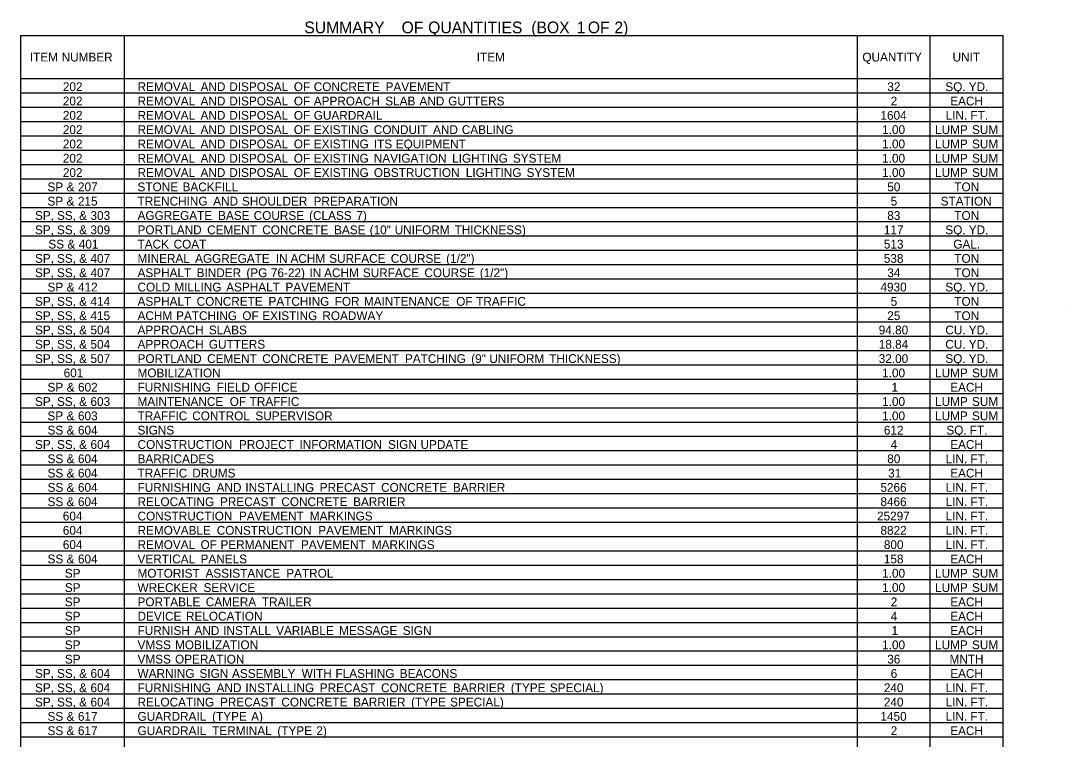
# Model space of a CAD drawing. Extents: x 107 to 7866, y 32 to 1473.
# Drawn here: x 6428 to 7140, y 553 to 1043 of the extents above; entities that cross this region are included whole.
import ezdxf

# ---------------------------------------------------------------- set-up
doc = ezdxf.new("R2010")
doc.units = 0
doc.layers.add('Default', color=7, linetype='Continuous')

msp = doc.modelspace()

# ---------------------------------------------------------------- linework, layer by layer
at = {"layer": 'Default'}
for p, q in [((6427.83, 1032.7), (7097.17, 1032.7)), ((6427.83, 67.45), (6427.83, 1032.7)), ((6427.83, 67.45), (6427.83, 1032.7)), ((6498.52, 155.2), (6498.52, 1032.7)), ((6997.72, 1032.7), (7097.17, 1032.7)), ((6997.72, 67.45), (6997.72, 1032.7)), ((7047.45, 67.45), (7047.45, 1032.7)), ((7047.45, 155.2), (7047.45, 1032.7)), ((7097.17, 67.45), (7097.17, 1032.7)), ((6427.83, 1003.45), (7097.17, 1003.45)), ((6427.83, 1003.45), (7097.17, 1003.45)), ((6498.52, 340.45), (6498.52, 1003.45)), ((6997.72, 340.45), (6997.72, 1003.45)), ((6427.83, 993.7), (7097.17, 993.7)), ((6427.83, 983.95), (7097.17, 983.95)), ((6427.83, 974.2), (7097.17, 974.2)), ((6427.83, 964.45), (7097.17, 964.45)), ((6427.83, 954.7), (7097.17, 954.7)), ((6427.83, 944.95), (7097.17, 944.95)), ((6427.83, 935.2), (7097.17, 935.2)), ((6427.83, 925.45), (7097.17, 925.45)), ((6427.83, 915.7), (7097.17, 915.7)), ((6427.83, 905.95), (7097.17, 905.95)), ((6427.83, 896.2), (7097.17, 896.2)), ((6427.83, 886.45), (7097.17, 886.45)), ((6427.83, 876.7), (7097.17, 876.7)), ((6427.83, 866.95), (7097.17, 866.95)), ((6427.83, 857.2), (7097.17, 857.2)), ((6427.83, 847.45), (7097.17, 847.45)), ((7139.96, 848.72), (7139.96, 848.72)), ((6427.83, 837.7), (7097.17, 837.7)), ((6427.83, 827.95), (7097.17, 827.95)), ((6427.83, 818.2), (7097.17, 818.2)), ((6427.83, 808.45), (7097.17, 808.45)), ((6427.83, 798.7), (7097.17, 798.7)), ((6427.83, 788.95), (7097.17, 788.95)), ((6427.83, 779.2), (7097.17, 779.2)), ((6427.83, 769.45), (7097.17, 769.45)), ((6427.83, 759.7), (7097.17, 759.7)), ((6427.83, 749.95), (7097.17, 749.95)), ((6427.83, 740.2), (7097.17, 740.2)), ((6427.83, 730.45), (7097.17, 730.45)), ((6427.83, 720.7), (7097.17, 720.7)), ((6427.83, 710.95), (7097.17, 710.95)), ((6427.83, 701.2), (7097.17, 701.2)), ((6427.83, 691.45), (7097.17, 691.45)), ((6427.83, 681.7), (7097.17, 681.7)), ((6427.83, 671.95), (7097.17, 671.95)), ((6427.83, 662.2), (7097.17, 662.2)), ((6427.83, 652.45), (7097.17, 652.45)), ((6427.83, 642.7), (7097.17, 642.7)), ((6427.83, 632.95), (7097.17, 632.95)), ((6427.83, 623.2), (7097.17, 623.2)), ((6427.83, 613.45), (7097.17, 613.45)), ((6427.83, 603.7), (7097.17, 603.7)), ((6427.83, 593.95), (7097.17, 593.95)), ((6427.83, 584.2), (7097.17, 584.2)), ((6427.83, 574.45), (7097.17, 574.45)), ((6427.83, 564.7), (7097.17, 564.7)), ((6427.83, 554.95), (7097.17, 554.95))]:
    msp.add_line(p, q, dxfattribs=at)

# ---------------------------------------------------------------- texts
for s, height, p in [('                                          SUMMARY', 8, (6496.1, 1034.3)), (' OF', 8, (6684.23, 1034.3)), (' QUANTITIES', 8, (6702.34, 1034.3)), (' (BOX', 8, (6772.59, 1034.3)), (' 1', 8, (6803.63, 1034.3)), (' OF', 8, (6811.13, 1034.3)), (' 2)', 8, (6829.24, 1034.3)), ('ITEM', 6, (6433.92, 1015.08)), (' NUMBER', 6, (6453.35, 1015.08)), ('ITEM', 6, (6738.41, 1015.08)), ('QUANTITY', 6, (7001.15, 1015.08)), ('UNIT', 6, (7062.62, 1015.08)), ('202', 6, (6456.41, 994.9)), ('REMOVAL', 6, (6507.3, 994.9)), (' AND', 6, (6548, 994.9)), (' DISPOSAL', 6, (6567.58, 994.9)), (' OF', 6, (6611.55, 994.9)), (' CONCRETE', 6, (6625.13, 994.9)), (' PAVEMENT', 6, (6674.06, 994.9)), ('32', 6, (7018.14, 994.9)), ('SQ.', 6, (7057.67, 994.9)), (' YD.', 6, (7071.38, 994.9)), ('202', 6, (6456.41, 985.15)), ('REMOVAL', 6, (6507.3, 985.15)), (' AND', 6, (6548, 985.15)), (' DISPOSAL', 6, (6567.58, 985.15)), (' OF', 6, (6611.55, 985.15)), (' APPROACH', 6, (6625.13, 985.15)), (' SLAB', 6, (6673.84, 985.15)), (' AND', 6, (6697.16, 985.15)), (' GUTTERS', 6, (6716.74, 985.15)), ('2', 6, (7020.47, 985.15)), ('EACH', 6, (7061, 985.15)), ('202', 6, (6456.41, 975.4)), ('REMOVAL', 6, (6507.3, 975.4)), (' AND', 6, (6548, 975.4)), (' DISPOSAL', 6, (6567.58, 975.4)), (' OF', 6, (6611.55, 975.4)), (' GUARDRAIL', 6, (6625.13, 975.4)), ('1604', 6, (7013.47, 975.4)), ('LIN.', 6, (7057.9, 975.4)), (' FT.', 6, (7072.54, 975.4)), ('202', 6, (6456.41, 965.65)), ('REMOVAL', 6, (6507.3, 965.65)), (' AND', 6, (6548, 965.65)), (' DISPOSAL', 6, (6567.58, 965.65)), (' OF', 6, (6611.55, 965.65)), (' EXISTING', 6, (6625.13, 965.65)), (' CONDUIT', 6, (6666.07, 965.65)), (' AND', 6, (6706.42, 965.65)), (' CABLING', 6, (6726, 965.65)), ('1.00', 6, (7014.63, 965.65)), ('LUMP', 6, (7050.68, 965.65)), (' SUM', 6, (7073.61, 965.65)), ('202', 6, (6456.41, 955.9)), ('REMOVAL', 6, (6507.3, 955.9)), (' AND', 6, (6548, 955.9)), (' DISPOSAL', 6, (6567.58, 955.9)), (' OF', 6, (6611.55, 955.9)), (' EXISTING', 6, (6625.13, 955.9)), (' ITS', 6, (6666.07, 955.9)), (' EQUIPMENT', 6, (6681, 955.9)), ('1.00', 6, (7014.63, 955.9)), ('LUMP', 6, (7050.68, 955.9)), (' SUM', 6, (7073.61, 955.9)), ('202', 6, (6456.41, 946.15)), ('REMOVAL', 6, (6507.3, 946.15)), (' AND', 6, (6548, 946.15)), (' DISPOSAL', 6, (6567.58, 946.15)), (' OF', 6, (6611.55, 946.15)), (' EXISTING', 6, (6625.13, 946.15)), (' NAVIGATION', 6, (6666.07, 946.15)), (' LIGHTING', 6, (6719.42, 946.15)), (' SYSTEM', 6, (6760.81, 946.15)), ('1.00', 6, (7014.63, 946.15)), ('LUMP', 6, (7050.68, 946.15)), (' SUM', 6, (7073.61, 946.15)), ('202', 6, (6456.41, 936.4)), ('REMOVAL', 6, (6507.3, 936.4)), (' AND', 6, (6548, 936.4)), (' DISPOSAL', 6, (6567.58, 936.4)), (' OF', 6, (6611.55, 936.4)), (' EXISTING', 6, (6625.13, 936.4)), (' OBSTRUCTION', 6, (6666.07, 936.4)), (' LIGHTING', 6, (6728.73, 936.4)), (' SYSTEM', 6, (6770.12, 936.4)), ('1.00', 6, (7014.63, 936.4)), ('LUMP', 6, (7050.68, 936.4)), (' SUM', 6, (7073.61, 936.4)), ('SP', 6, (6445.94, 926.65)), (' &', 6, (6456.76, 926.65)), (' 207', 6, (6464.49, 926.65)), ('STONE', 6, (6507.3, 926.65)), (' BACKFILL', 6, (6535.73, 926.65)), ('50', 6, (7018.12, 926.65)), ('TON', 6, (7063.8, 926.65)), ('SP', 6, (6445.92, 916.9)), (' &', 6, (6456.74, 916.9)), (' 215', 6, (6464.46, 916.9)), ('TRENCHING', 6, (6507.3, 916.9)), (' AND', 6, (6556.61, 916.9)), (' SHOULDER', 6, (6576.19, 916.9)), (' PREPARATION', 6, (6624.99, 916.9)), ('5', 6, (7020.42, 916.9)), ('STATION', 6, (7054.48, 916.9)), ('SP,', 6, (6437.42, 907.15)), (' SS,', 6, (6450.18, 907.15)), (' &', 6, (6465.28, 907.15)), (' 303', 6, (6473.01, 907.15)), ('AGGREGATE', 6, (6507.3, 907.15)), (' BASE', 6, (6559.96, 907.15)), (' COURSE', 6, (6584.21, 907.15)), (' (CLASS', 6, (6621.96, 907.15)), (' 7)', 6, (6654.14, 907.15)), ('83', 6, (7018.11, 907.15)), ('TON', 6, (7063.8, 907.15)), ('SP,', 6, (6437.41, 897.4)), (' SS,', 6, (6450.18, 897.4)), (' &', 6, (6465.28, 897.4)), (' 309', 6, (6473, 897.4)), ('PORTLAND', 6, (6507.3, 897.4)), (' CEMENT', 6, (6552.5, 897.4)), (' CONCRETE', 6, (6590.06, 897.4)), (' BASE', 6, (6638.99, 897.4)), (' (10"', 6, (6663.24, 897.4)), (' UNIFORM', 6, (6680.26, 897.4)), (' THICKNESS)', 6, (6721.08, 897.4)), ('117', 6, (7015.78, 897.4)), ('SQ.', 6, (7057.67, 897.4)), (' YD.', 6, (7071.38, 897.4)), ('SS', 6, (6446.56, 887.65)), (' &', 6, (6457.3, 887.65)), (' 401', 6, (6465.03, 887.65)), ('TACK', 6, (6507.3, 887.65)), (' COAT', 6, (6529.64, 887.65)), ('513', 6, (7015.78, 887.65)), ('GAL.', 6, (7063.12, 887.65)), ('SP,', 6, (6437.42, 877.9)), (' SS,', 6, (6450.18, 877.9)), (' &', 6, (6465.28, 877.9)), (' 407', 6, (6473.01, 877.9)), ('MINERAL', 6, (6507.3, 877.9)), (' AGGREGATE', 6, (6544.26, 877.9)), (' IN', 6, (6599.26, 877.9)), (' ACHM', 6, (6609.28, 877.9)), (' SURFACE', 6, (6635.66, 877.9)), (' COURSE', 6, (6677.61, 877.9)), (' (1/2")', 6, (6715.36, 877.9)), ('538', 6, (7015.78, 877.9)), ('TON', 6, (7063.8, 877.9)), ('SP,', 6, (6437.42, 868.15)), (' SS,', 6, (6450.18, 868.15)), (' &', 6, (6465.28, 868.15)), (' 407', 6, (6473.01, 868.15)), ('ASPHALT', 6, (6507.3, 868.15)), (' BINDER', 6, (6545.33, 868.15)), (' (PG', 6, (6579.23, 868.15)), (' 76-22)', 6, (6595.93, 868.15)), (' IN', 6, (6622.18, 868.15)), (' ACHM', 6, (6632.2, 868.15)), (' SURFACE', 6, (6658.58, 868.15)), (' COURSE', 6, (6700.53, 868.15)), (' (1/2")', 6, (6738.28, 868.15)), ('34', 6, (7018.13, 868.15)), ('TON', 6, (7063.8, 868.15)), ('SP', 6, (6445.97, 858.4)), (' &', 6, (6456.79, 858.4)), (' 412', 6, (6464.52, 858.4)), ('COLD', 6, (6507.3, 858.4)), (' MILLING', 6, (6530.14, 858.4)), (' ASPHALT', 6, (6565.48, 858.4)), (' PAVEMENT', 6, (6605.84, 858.4)), ('4930', 6, (7013.46, 858.4)), ('SQ.', 6, (7057.67, 858.4)), (' YD.', 6, (7071.38, 858.4)), ('SP,', 6, (6437.43, 848.65)), (' SS,', 6, (6450.2, 848.65)), (' &', 6, (6465.29, 848.65)), (' 414', 6, (6473.02, 848.65)), ('ASPHALT', 6, (6507.3, 848.65)), (' CONCRETE', 6, (6545.33, 848.65)), (' PATCHING', 6, (6594.26, 848.65)), (' FOR', 6, (6639.39, 848.65)), (' MAINTENANCE', 6, (6659.3, 848.65)), (' OF', 6, (6722.2, 848.65)), (' TRAFFIC', 6, (6735.79, 848.65)), ('5', 6, (7020.42, 848.65)), ('TON', 6, (7063.8, 848.65)), ('SP,', 6, (6437.39, 838.9)), (' SS,', 6, (6450.16, 838.9)), (' &', 6, (6465.26, 838.9)), (' 415', 6, (6472.99, 838.9)), ('ACHM', 6, (6507.3, 838.9)), (' PATCHING', 6, (6531.35, 838.9)), (' OF', 6, (6576.47, 838.9)), (' EXISTING', 6, (6590.06, 838.9)), (' ROADWAY', 6, (6631, 838.9)), ('25', 6, (7018.09, 838.9)), ('TON', 6, (7063.8, 838.9)), ('SP,', 6, (6437.43, 829.15)), (' SS,', 6, (6450.2, 829.15)), (' &', 6, (6465.29, 829.15)), (' 504', 6, (6473.02, 829.15)), ('APPROACH', 6, (6507.3, 829.15)), (' SLABS', 6, (6553.68, 829.15)), ('94.80', 6, (7012.3, 829.15)), ('CU.', 6, (7057.67, 829.15)), (' YD.', 6, (7071.37, 829.15)), ('SP,', 6, (6437.43, 819.4)), (' SS,', 6, (6450.2, 819.4)), (' &', 6, (6465.29, 819.4)), (' 504', 6, (6473.02, 819.4)), ('APPROACH', 6, (6507.3, 819.4)), (' GUTTERS', 6, (6553.68, 819.4)), ('18.84', 6, (7012.3, 819.4)), ('CU.', 6, (7057.67, 819.4)), (' YD.', 6, (7071.37, 819.4)), ('SP,', 6, (6437.42, 809.65)), (' SS,', 6, (6450.18, 809.65)), (' &', 6, (6465.28, 809.65)), (' 507', 6, (6473.01, 809.65)), ('PORTLAND', 6, (6507.3, 809.65)), (' CEMENT', 6, (6552.5, 809.65)), (' CONCRETE', 6, (6590.06, 809.65)), (' PAVEMENT', 6, (6638.99, 809.65)), (' PATCHING', 6, (6687.27, 809.65)), (' (9"', 6, (6732.4, 809.65)), (' UNIFORM', 6, (6744.76, 809.65)), (' THICKNESS)', 6, (6785.57, 809.65)), ('32.00', 6, (7012.3, 809.65)), ('SQ.', 6, (7057.67, 809.65)), (' YD.', 6, (7071.38, 809.65)), ('601', 6, (6456.96, 799.9)), ('MOBILIZATION', 6, (6507.3, 799.9)), ('1.00', 6, (7014.63, 799.9)), ('LUMP', 6, (7050.68, 799.9)), (' SUM', 6, (7073.61, 799.9)), ('SP', 6, (6445.97, 790.15)), (' &', 6, (6456.79, 790.15)), (' 602', 6, (6464.52, 790.15)), ('FURNISHING', 6, (6507.3, 790.15)), (' FIELD', 6, (6558.94, 790.15)), (' OFFICE', 6, (6584.57, 790.15)), ('1', 6, (7021.02, 790.15)), ('EACH', 6, (7061, 790.15)), ('SP,', 6, (6437.42, 780.4)), (' SS,', 6, (6450.18, 780.4)), (' &', 6, (6465.28, 780.4)), (' 603', 6, (6473.01, 780.4)), ('MAINTENANCE', 6, (6507.3, 780.4)), (' OF', 6, (6567.87, 780.4)), (' TRAFFIC', 6, (6581.46, 780.4)), ('1.00', 6, (7014.63, 780.4)), ('LUMP', 6, (7050.68, 780.4)), (' SUM', 6, (7073.61, 780.4)), ('SP', 6, (6445.94, 770.65)), (' &', 6, (6456.76, 770.65)), (' 603', 6, (6464.49, 770.65)), ('TRAFFIC', 6, (6507.3, 770.65)), (' CONTROL', 6, (6542.36, 770.65)), (' SUPERVISOR', 6, (6585.38, 770.65)), ('1.00', 6, (7014.63, 770.65)), ('LUMP', 6, (7050.68, 770.65)), (' SUM', 6, (7073.61, 770.65)), ('SS', 6, (6445.99, 760.9)), (' &', 6, (6456.74, 760.9)), (' 604', 6, (6464.46, 760.9)), ('SIGNS', 6, (6507.3, 760.9)), ('612', 6, (7015.81, 760.9)), ('SQ.', 6, (7058.37, 760.9)), (' FT.', 6, (7072.08, 760.9)), ('SP,', 6, (6437.43, 751.15)), (' SS,', 6, (6450.2, 751.15)), (' &', 6, (6465.29, 751.15)), (' 604', 6, (6473.02, 751.15)), ('CONSTRUCTION', 6, (6507.3, 751.15)), (' PROJECT', 6, (6574.15, 751.15)), (' INFORMATION', 6, (6615.44, 751.15)), (' SIGN', 6, (6675.76, 751.15)), (' UPDATE', 6, (6697.9, 751.15)), ('4', 6, (7020.46, 751.15)), ('EACH', 6, (7061, 751.15)), ('SS', 6, (6445.99, 741.4)), (' &', 6, (6456.74, 741.4)), (' 604', 6, (6464.46, 741.4)), ('BARRICADES', 6, (6507.3, 741.4)), ('80', 6, (7018.12, 741.4)), ('LIN.', 6, (7057.9, 741.4)), (' FT.', 6, (7072.54, 741.4)), ('SS', 6, (6445.99, 731.65)), (' &', 6, (6456.74, 731.65)), (' 604', 6, (6464.46, 731.65)), ('TRAFFIC', 6, (6507.3, 731.65)), (' DRUMS', 6, (6542.36, 731.65)), ('31', 6, (7018.69, 731.65)), ('EACH', 6, (7061, 731.65)), ('SS', 6, (6445.99, 721.9)), (' &', 6, (6456.74, 721.9)), (' 604', 6, (6464.46, 721.9)), ('FURNISHING', 6, (6507.3, 721.9)), (' AND', 6, (6558.94, 721.9)), (' INSTALLING', 6, (6578.52, 721.9)), (' PRECAST', 6, (6629.23, 721.9)), (' CONCRETE', 6, (6671, 721.9)), (' BARRIER', 6, (6719.92, 721.9)), ('5266', 6, (7013.45, 721.9)), ('LIN.', 6, (7057.9, 721.9)), (' FT.', 6, (7072.54, 721.9)), ('SS', 6, (6445.99, 712.15)), (' &', 6, (6456.74, 712.15)), (' 604', 6, (6464.46, 712.15)), ('RELOCATING', 6, (6507.3, 712.15)), (' PRECAST', 6, (6561.27, 712.15)), (' CONCRETE', 6, (6603.03, 712.15)), (' BARRIER', 6, (6651.96, 712.15)), ('8466', 6, (7013.45, 712.15)), ('LIN.', 6, (7057.9, 712.15)), (' FT.', 6, (7072.54, 712.15)), ('604', 6, (6456.39, 702.4)), ('CONSTRUCTION', 6, (6507.3, 702.4)), (' PAVEMENT', 6, (6574.15, 702.4)), (' MARKINGS', 6, (6622.43, 702.4)), ('25297', 6, (7011.12, 702.4)), ('LIN.', 6, (7057.9, 702.4)), (' FT.', 6, (7072.54, 702.4)), ('604', 6, (6456.39, 692.65)), ('REMOVABLE', 6, (6507.3, 692.65)), (' CONSTRUCTION', 6, (6559.03, 692.65)), (' PAVEMENT', 6, (6628.21, 692.65)), (' MARKINGS', 6, (6676.49, 692.65)), ('8822', 6, (7013.48, 692.65)), ('LIN.', 6, (7057.9, 692.65)), (' FT.', 6, (7072.54, 692.65)), ('604', 6, (6456.39, 682.9)), ('REMOVAL', 6, (6507.3, 682.9)), (' OF', 6, (6548, 682.9)), (' PERMANENT', 6, (6561.58, 682.9)), (' PAVEMENT', 6, (6616.38, 682.9)), (' MARKINGS', 6, (6664.67, 682.9)), ('800', 6, (7015.79, 682.9)), ('LIN.', 6, (7057.9, 682.9)), (' FT.', 6, (7072.54, 682.9)), ('SS', 6, (6445.99, 673.15)), (' &', 6, (6456.74, 673.15)), (' 604', 6, (6464.46, 673.15)), ('VERTICAL', 6, (6507.3, 673.15)), (' PANELS', 6, (6548, 673.15)), ('158', 6, (7015.78, 673.15)), ('EACH', 6, (7061, 673.15)), ('SP', 6, (6457.77, 663.4)), ('MOTORIST', 6, (6507.3, 663.4)), (' ASSISTANCE', 6, (6551.37, 663.4)), (' PATROL', 6, (6606.37, 663.4)), ('1.00', 6, (7014.63, 663.4)), ('LUMP', 6, (7050.68, 663.4)), (' SUM', 6, (7073.61, 663.4)), ('SP', 6, (6457.77, 653.65)), ('WRECKER', 6, (6507.3, 653.65)), (' SERVICE', 6, (6550.04, 653.65)), ('1.00', 6, (7014.63, 653.65)), ('LUMP', 6, (7050.68, 653.65)), (' SUM', 6, (7073.61, 653.65)), ('SP', 6, (6457.77, 643.9)), ('PORTABLE', 6, (6507.3, 643.9)), (' CAMERA', 6, (6551.58, 643.9)), (' TRAILER', 6, (6589.79, 643.9)), ('2', 6, (7020.47, 643.9)), ('EACH', 6, (7061, 643.9)), ('SP', 6, (6457.77, 634.15)), ('DEVICE', 6, (6507.3, 634.15)), (' RELOCATION', 6, (6538.06, 634.15)), ('4', 6, (7020.46, 634.15)), ('EACH', 6, (7061, 634.15)), ('SP', 6, (6457.77, 624.4)), ('FURNISH', 6, (6507.3, 624.4)), (' AND', 6, (6543.88, 624.4)), (' INSTALL', 6, (6563.46, 624.4)), (' VARIABLE', 6, (6599.5, 624.4)), (' MESSAGE', 6, (6642.39, 624.4)), (' SIGN', 6, (6685.74, 624.4)), ('1', 6, (7021.02, 624.4)), ('EACH', 6, (7061, 624.4)), ('SP', 6, (6457.77, 614.65)), ('VMSS', 6, (6507.3, 614.65)), (' MOBILIZATION', 6, (6530.62, 614.65)), ('1.00', 6, (7014.63, 614.65)), ('LUMP', 6, (7050.68, 614.65)), (' SUM', 6, (7073.61, 614.65)), ('SP', 6, (6457.77, 604.9)), ('VMSS', 6, (6507.3, 604.9)), (' OPERATION', 6, (6530.62, 604.9)), ('36', 6, (7018.11, 604.9)), ('MNTH', 6, (7060.54, 604.9)), ('SP,', 6, (6437.43, 595.15)), (' SS,', 6, (6450.2, 595.15)), (' &', 6, (6465.29, 595.15)), (' 604', 6, (6473.02, 595.15)), ('WARNING', 6, (6507.3, 595.15)), (' SIGN', 6, (6547.29, 595.15)), (' ASSEMBLY', 6, (6569.43, 595.15)), (' WITH', 6, (6616.89, 595.15)), (' FLASHING', 6, (6639.96, 595.15)), (' BEACONS', 6, (6683.69, 595.15)), ('6', 6, (7020.44, 595.15)), ('EACH', 6, (7061, 595.15)), ('SP,', 6, (6437.43, 585.4)), (' SS,', 6, (6450.2, 585.4)), (' &', 6, (6465.29, 585.4)), (' 604', 6, (6473.02, 585.4)), ('FURNISHING', 6, (6507.3, 585.4)), (' AND', 6, (6558.94, 585.4)), (' INSTALLING', 6, (6578.52, 585.4)), (' PRECAST', 6, (6629.23, 585.4)), (' CONCRETE', 6, (6671, 585.4)), (' BARRIER', 6, (6719.92, 585.4)), (' (TYPE', 6, (6759.41, 585.4)), (' SPECIAL)', 6, (6785.98, 585.4)), ('240', 6, (7015.79, 585.4)), ('LIN.', 6, (7057.9, 585.4)), (' FT.', 6, (7072.54, 585.4)), ('SP,', 6, (6437.43, 575.65)), (' SS,', 6, (6450.2, 575.65)), (' &', 6, (6465.29, 575.65)), (' 604', 6, (6473.02, 575.65)), ('RELOCATING', 6, (6507.3, 575.65)), (' PRECAST', 6, (6561.27, 575.65)), (' CONCRETE', 6, (6603.03, 575.65)), (' BARRIER', 6, (6651.96, 575.65)), (' (TYPE', 6, (6691.45, 575.65)), (' SPECIAL)', 6, (6718.02, 575.65)), ('240', 6, (7015.79, 575.65)), ('LIN.', 6, (7057.9, 575.65)), (' FT.', 6, (7072.54, 575.65)), ('SS', 6, (6445.97, 565.9)), (' &', 6, (6456.72, 565.9)), (' 617', 6, (6464.45, 565.9)), ('GUARDRAIL', 6, (6507.3, 565.9)), (' (TYPE', 6, (6555.91, 565.9)), (' A)', 6, (6582.48, 565.9)), ('1450', 6, (7013.46, 565.9)), ('LIN.', 6, (7057.9, 565.9)), (' FT.', 6, (7072.54, 565.9)), ('SS', 6, (6445.97, 556.15)), (' &', 6, (6456.72, 556.15)), (' 617', 6, (6464.45, 556.15)), ('GUARDRAIL', 6, (6507.3, 556.15)), (' TERMINAL', 6, (6555.91, 556.15)), (' (TYPE', 6, (6600.33, 556.15)), (' 2)', 6, (6626.9, 556.15)), ('2', 6, (7020.47, 556.15)), ('EACH', 6, (7061, 556.15))]:
    msp.add_text(s, height=height, dxfattribs=at).set_placement(p)

doc.saveas('drawing.dxf')
